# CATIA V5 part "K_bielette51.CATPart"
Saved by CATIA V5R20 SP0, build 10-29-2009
Part number: biellette 51
Publications: "demi largeur balancier", "epaisseur pieces", "rayon congé", "Plan.-30", "liaison 51/50", "liaison 51/38 sur 51", "liaison 51/70 sur 51"
Bounding box of the stored display mesh (mm): x -30 to 0, y -575 to -470.002, z 640.005 to 790
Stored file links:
  G:\Khaled_CFAO_2011\SIL\SIL_GR2\mdardier\Khaled\CAD_ThinkMOTION\K_bielette51.CATPart
  G:\Khaled_CFAO_2011\SIL\SIL_GR2\mdardier\Khaled\CAD_ThinkMOTION\K_ass_tandem.CATProduct
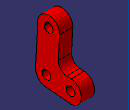
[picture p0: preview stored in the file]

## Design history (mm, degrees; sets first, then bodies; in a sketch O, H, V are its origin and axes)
External parameters (linked from other documents)
  `External.demi largeur balancier` = 50 mm
  `External.epaisseur pieces` = 30 mm
  `External.rayon congé` = 20 mm
Set1
  Plane1 "Plan.-30": linked copy from another document
  Point1 "liaison 51/50": linked copy from another document
  Point2 "liaison 51/38 sur 51": linked copy from another document
  Point3 "liaison 51/70 sur 51": linked copy from another document
Body1 (main body)
  Sketch1 on Plane1, origin (-30, 0, 0), H (0, 1, 0), V (0, 0, 1)
    construction line L1 (-545, 765) -> (-550, 670)
    point P1 (-545, 765)
    point P2 (-550, 670)
    line L2 (-520.0346, 763.686) -> (-523.8311, 691.552)
    line L3 (-574.9654, 671.314) -> (-569.9654, 766.314)
    arc A1 centre (-550, 670) radius 25 from (-552.2634, 645.1027) to (-574.9654, 671.314) cw
    arc A2 centre (-545, 765) radius 25 from (-569.9654, 766.314) to (-520.0346, 763.686) cw
    reference projected point E1 (-545, 765) from Point1
    reference projected point E2 (-550, 670) from Point2
    arc A3 centre (-495, 665) radius 25 from (-497.2634, 640.1027) to (-493.686, 689.9654) ccw
    point P6 (-495, 665)
    reference projected point E3 (-495, 665) from Point3
    circle A4 centre (-545, 765) radius 10
    point P7 (-545, 765)
    reference projected point E4 (-545, 765) from Point1
    circle A5 centre (-550, 670) radius 10
    point P8 (-550, 670)
    reference projected point E5 (-550, 670) from Point2
    circle A6 centre (-495, 665) radius 10
    point P9 (-495, 665)
    reference projected point E6 (-495, 665) from Point3
    line L4 (-493.686, 689.9654) -> (-523.8311, 691.552)
    line L5 (-497.2634, 640.1027) -> (-552.2634, 645.1027)
    distance L1 L2 = 25 {= `External.demi largeur balancier` /2}
    radius A3 = 25 {= `External.demi largeur balancier` /2}
    radius A4 = 10 {= `External.demi largeur balancier` /5}
    radius A5 = 10 {= `External.demi largeur balancier` /5}
    radius A6 = 10 {= `External.demi largeur balancier` /5}
    tangency: A1 L2, A2 L2, A1 L3, A2 L3, L5 A3, L5 A1, L4 A3
    coincidence: P1 E1, P2 E2, P6 E3, P7 E4, P8 E5, P9 E6
    perpendicularity: L4 L2
  Pad1: profile Sketch1, direction (1, 0, 0), length 30 {= `External.epaisseur pieces`}
  Fillet1: radius 20 {= `External.rayon congé`}, on edge [face of Pad1 from Sketch1.L2 | face of Pad1 from Sketch1.L4]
